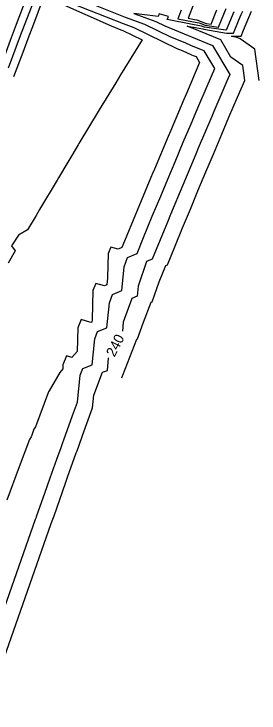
# Model space of a CAD drawing. Extents: x 1160447 to 1162032, y 616022 to 618272.
# Drawn here: x 1160997.8 to 1161058.4, y 616560 to 616733 of the extents above; entities that cross this region are included whole.
import ezdxf

# ---------------------------------------------------------------- set-up
doc = ezdxf.new("R2010")
doc.units = 0
doc.layers.add('D_Contours_Major', color=7, linetype='Continuous')
doc.layers.add('D_Contours_Minor', color=7, linetype='Continuous')

msp = doc.modelspace()

# ---------------------------------------------------------------- linework, layer by layer
at = {"layer": 'D_Contours_Major'}
for points in [[(1161052.15, 616733.51), (1161050.26, 616729), (1161050.26, 616729), (1161050.25, 616729), (1161044.93, 616729.69), (1161044.16, 616729.99), (1161041.98, 616730.39), (1161035.73, 616731.56), (1161036.01, 616732.31), (1161033.72, 616732.98), (1161033.46, 616732.36), (1161027.47, 616733.11), (1161032.93, 616731.08), (1161035.14, 616730.01), (1161040.9, 616727.68), (1161041.72, 616727.31), (1161046.93, 616725.2), (1161051.16, 616717.97), (1161050.72, 616716.93), (1161047.27, 616708.87), (1161046.73, 616707.59), (1161043.41, 616699.75), (1161042.78, 616698.24), (1161039.58, 616690.62), (1161036.56, 616683.35), (1161035.78, 616681.47), (1161034.97, 616679.5), (1161032.02, 616672.31), (1161030.63, 616671.71), (1161028.52, 616665.63), (1161028.29, 616663.13), (1161026.96, 616662.58), (1161024.86, 616656.7), (1161024.64, 616654.49)], [(1160974.68, 616514.45), (1161006.96, 616606.59), (1161007.29, 616607.53), (1161007.74, 616608.8), (1161010.59, 616616.88), (1161011.09, 616618.29), (1161013.25, 616624.34), (1161013.42, 616624.81), (1161013.92, 616626.21), (1161014.8, 616628.63), (1161017.28, 616635.52), (1161017.6, 616638.61), (1161019.75, 616644.29), (1161020.92, 616644.74), (1161021.22, 616647.76), (1161021.25, 616647.83)]]:
    msp.add_lwpolyline(points, dxfattribs=at)
at = {"layer": 'D_Contours_Minor'}
for points in [[(1161001.2, 616737.79), (1160998.4, 616730.39), (1160997.63, 616728.36), (1160996.89, 616726.4), (1160994.09, 616718.91), (1160991.2, 616711.11), (1160990.58, 616709.45), (1160989.71, 616707.06)], [(1160958.66, 616480.83), (1161003.19, 616607.91), (1161003.38, 616608.47), (1161003.52, 616608.85), (1161005.48, 616614.4), (1161006.82, 616618.2), (1161008.46, 616622.82), (1161009.48, 616625.68), (1161009.91, 616626.89), (1161010.15, 616627.55), (1161012.34, 616633.61), (1161013.52, 616636.88), (1161014.21, 616643.57), (1161014.84, 616645.21), (1161017.16, 616646.11), (1161017.81, 616652.57), (1161018.48, 616654.38), (1161020.83, 616655.33), (1161021.44, 616661.5), (1161022.17, 616663.54), (1161024.54, 616664.53), (1161025.1, 616670.41), (1161025.89, 616672.68), (1161028.27, 616673.72), (1161029.87, 616677.61), (1161032.04, 616682.89), (1161034.13, 616687.91), (1161035.85, 616692.05), (1161037.67, 616696.4), (1161039.68, 616701.2), (1161041.61, 616705.76), (1161043.55, 616710.33), (1161045.6, 616715.12), (1161047.45, 616719.45), (1161044.88, 616723.82), (1161041.73, 616725.1), (1161040.15, 616725.8), (1161036.61, 616727.23), (1161030.19, 616730.35), (1161025.44, 616732.11), (1161017.96, 616735.04)], [(1161012.24, 616735.52), (1161024.84, 616730.59), (1161027.46, 616729.62), (1161038.09, 616724.46), (1161039.4, 616723.92), (1161041.74, 616722.89), (1161042.15, 616722.72), (1161042.84, 616722.44), (1161043.73, 616720.92), (1161040.47, 616713.31), (1161039.82, 616711.79), (1161036.5, 616703.93), (1161035.95, 616702.65), (1161032.56, 616694.55), (1161032.11, 616693.49), (1161031.69, 616692.48), (1161028.31, 616684.31), (1161024.78, 616675.73), (1161024.53, 616675.13), (1161023.6, 616674.73), (1161021.8, 616675.25), (1161021.14, 616673.66), (1161020.95, 616667.64), (1161020.79, 616665.92), (1161020.22, 616665.69), (1161018.11, 616666.3), (1161017.37, 616664.5), (1161017.14, 616657.36), (1161017.08, 616656.71), (1161016.87, 616656.62), (1161014.44, 616657.32), (1161013.63, 616655.32), (1161013.43, 616649.44), (1161012.18, 616647.92), (1161010.8, 616648.32), (1161009.92, 616646.14), (1161009.88, 616645.12), (1161009.15, 616644.22), (1161006.54, 616639.69), (1161006.4, 616639.44), (1161003.15, 616630.77), (1161002.79, 616630.17), (1161002.15, 616628.45), (1161002.06, 616628.31), (1161001.69, 616627.68), (1160999.14, 616620.91), (1160996.06, 616612.6)], [(1161009.57, 616735.51), (1161021.85, 616730), (1161024.23, 616729.07), (1161024.72, 616728.88), (1161029.49, 616726.57), (1161027.76, 616723.75), (1161024.2, 616717.93), (1161023, 616715.96), (1161018.93, 616709.26), (1161013.9, 616700.91), (1161013.69, 616700.57), (1161008.84, 616692.44), (1161008.48, 616691.85), (1161004.17, 616684.57), (1161003.31, 616683.11), (1161001.21, 616679.55), (1160999, 616678.2), (1160997.26, 616675.57), (1160998.16, 616674.35), (1160996.38, 616671.3)], [(1160996.5, 616719.65), (1160999.49, 616727.63), (1161002.72, 616736.17)], [(1160997.82, 616717.46), (1161000.08, 616723.5), (1161001.35, 616726.9), (1161002.73, 616730.53), (1161004.92, 616736.32)], [(1161042.3, 616735.54), (1161040.92, 616731.93), (1161042.48, 616731.63), (1161043.02, 616731.54), (1161045.31, 616730.64), (1161046.55, 616730.48), (1161048, 616733.96)], [(1161024.5, 616642.92), (1161024.67, 616643.37), (1161024.68, 616643.37), (1161024.74, 616643.55), (1161028.18, 616652.5), (1161028.34, 616652.56), (1161029.82, 616656.67), (1161031.76, 616661.62), (1161032.03, 616661.74), (1161033.76, 616666.66), (1161035.38, 616670.74), (1161035.76, 616670.9), (1161037.58, 616675.33), (1161039.52, 616680.05), (1161041.44, 616684.67), (1161043.31, 616689.18), (1161045.3, 616693.92), (1161047.14, 616698.3), (1161049.2, 616703.18), (1161050.99, 616707.41), (1161053.13, 616712.39), (1161054.88, 616716.5), (1161054.39, 616720.25), (1161051.47, 616722.31), (1161048.97, 616726.57), (1161041.71, 616729.53), (1161041.65, 616729.55), (1161040.62, 616729.97), (1161042.68, 616729.58), (1161044.49, 616729.26), (1161044.73, 616729.21), (1161044.74, 616729.21), (1161044.81, 616729.2), (1161050.4, 616728.2), (1161052.12, 616728.25), (1161053.36, 616731.23), (1161054.03, 616732.82), (1161054.37, 616733.63)], [(1161039.16, 616733.92), (1161038.32, 616731.74), (1161042.23, 616731.01), (1161043.59, 616730.76), (1161045.12, 616730.17), (1161048.4, 616729.74), (1161049.13, 616731.48), (1161050.32, 616734.32)], [(1161058.41, 616716.49), (1161057.39, 616724.28), (1161053.77, 616726.83), (1161053.6, 616726.92), (1161052.93, 616727.11), (1161052.18, 616727.3), (1161051.6, 616727.44), (1161053.97, 616727.51), (1161054.58, 616728.95), (1161055.88, 616732.07), (1161056.55, 616733.66)]]:
    msp.add_lwpolyline(points, dxfattribs=at)

# ---------------------------------------------------------------- texts
at = {"layer": 'D_Contours_Major'}
msp.add_text('240', height=2.49, rotation=62.8512, dxfattribs=at).set_placement((1161022.69, 616647.92))

doc.saveas('drawing.dxf')
